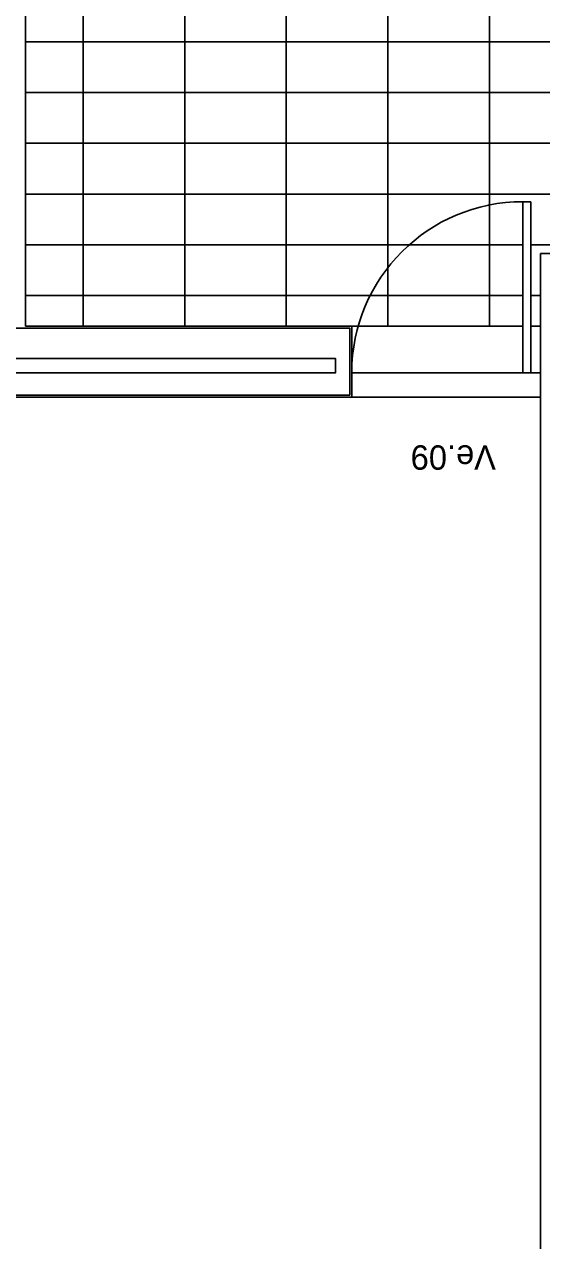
# Model space of a CAD drawing. Extents: x 1248 to 1356, y -443 to -224.
# Drawn here: x 1296.63 to 1299.18, y -243.58 to -237.59 of the extents above; entities that cross this region are included whole.
import ezdxf

# ---------------------------------------------------------------- set-up
doc = ezdxf.new("R2010")
doc.units = 0
for name, color, linetype in [('corte', 7, 'Continuous'), ('estereoctomias', 7, 'Continuous'), ('Level 1', 7, 'Continuous'), ('Level 10', 7, 'Continuous'), ('Level 2', 7, 'Continuous'), ('Level 3', 7, 'Continuous'), ('Level 40', 7, 'Continuous'), ('revestimentos', 7, 'Continuous')]:
    doc.layers.add(name, color=color, linetype=linetype)

msp = doc.modelspace()

# ---------------------------------------------------------------- linework, layer by layer
at = {"layer": 'corte'}
for p, q in [((1295.4133, -239.234), (1298.1608, -239.234)), ((1295.4133, -239.304), (1298.1608, -239.304)), ((1298.2308, -239.414), (1295.3433, -239.414))]:
    msp.add_line(p, q, dxfattribs=at)
at = {"layer": 'estereoctomias'}
msp.add_lwpolyline([(1298.2308, -239.414), (1295.3433, -239.414), (1295.3433, -239.234), (1295.4133, -239.234), (1295.4133, -239.269), (1295.4133, -239.304), (1298.1608, -239.304), (1298.1608, -239.234), (1295.3433, -239.234), (1295.3433, -239.084), (1298.2308, -239.084)], close=True, dxfattribs=at)
at = {"layer": 'Level 1'}
for p, q in [((1298.2308, -239.084), (1296.3983, -239.084)), ((1298.2308, -239.084), (1298.2308, -239.414)), ((1298.1608, -239.234), (1298.1608, -239.304))]:
    msp.add_line(p, q, dxfattribs=at)
at = {"layer": 'Level 10'}
for p, q in [((1296.9183, -231.874), (1296.9183, -239.074)), ((1297.4183, -231.874), (1297.4183, -239.074)), ((1297.9183, -237.1163), (1297.9183, -239.074)), ((1298.4183, -237.1163), (1298.4183, -239.074)), ((1298.9183, -237.1163), (1298.9183, -239.074)), ((1296.6333, -237.674), (1299.1415, -237.674)), ((1296.6633, -237.674), (1299.1415, -237.674)), ((1299.1415, -237.674), (1318.1944, -237.674)), ((1296.6333, -237.924), (1299.1415, -237.924)), ((1296.6633, -237.924), (1299.1415, -237.924)), ((1299.1415, -237.924), (1318.1944, -237.924)), ((1296.6333, -238.174), (1299.1415, -238.174)), ((1296.6433, -238.174), (1299.1415, -238.174)), ((1299.1415, -238.174), (1318.1944, -238.174)), ((1296.6333, -238.424), (1309.5183, -238.424)), ((1296.6333, -238.674), (1297.4356, -238.674)), ((1296.6633, -238.674), (1299.0831, -238.674)), ((1299.1231, -238.674), (1299.9727, -238.674)), ((1296.6333, -238.924), (1299.0831, -238.924)), ((1299.1231, -238.924), (1299.1708, -238.924))]:
    msp.add_line(p, q, dxfattribs=at)
at = {"layer": 'Level 2'}
for p, q in [((1299.0831, -238.4616), (1299.0831, -239.304)), ((1299.0831, -238.4616), (1299.1231, -238.4616)), ((1299.1231, -238.4616), (1299.1231, -239.304)), ((1299.0831, -239.074), (1298.2408, -239.074)), ((1299.1708, -239.074), (1299.1231, -239.074)), ((1299.1708, -239.304), (1298.2408, -239.304)), ((1299.1708, -239.424), (1298.2408, -239.424))]:
    msp.add_line(p, q, dxfattribs=at)
at = {"layer": 'Level 3'}
msp.add_arc((1299.0831, -239.304), 0.8424, 90, 180, dxfattribs=at)
at = {"layer": 'revestimentos'}
for p, q in [((1296.6333, -239.074), (1296.6333, -228.774)), ((1299.1708, -238.7163), (1299.9827, -238.7163)), ((1299.1708, -243.924), (1299.1708, -238.7163)), ((1298.2408, -239.074), (1296.6333, -239.074)), ((1298.2408, -239.074), (1298.2408, -239.424)), ((1298.2408, -239.424), (1295.3333, -239.424))]:
    msp.add_line(p, q, dxfattribs=at)

# ---------------------------------------------------------------- texts
at = {"layer": 'Level 40'}
msp.add_text('Ve.09', height=0.12, rotation=180.00001, dxfattribs=at).set_placement((1298.9504, -239.6615))

doc.saveas('drawing.dxf')
